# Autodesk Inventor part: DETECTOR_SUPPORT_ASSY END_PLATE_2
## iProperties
Shininess: 64.0
Length Units: 11272
Angle Units: 11279
Time Units: 11290
Mass Units: 11286
Length Display Precision: 3
Angle Display Precision: 2
Compacted: True
Part Number: DETECTOR_SUPPORT_ASSY END_PLATE_2
Document SubType Name: Modeling
Created: 2004-08
Designer: John Blackburn
Material: MILD_STEEL
Manufacturer: Standard
Standards Organization: Custom
Density: 0.0
Volumn: 0.0
Area: 0.0
PropertySet Name: Model Information
Control State: 0
Master: False
Checked Out: False
Author: John Blackburn
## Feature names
1. ExtrusionBlind1
2. ExtrusionThru1
